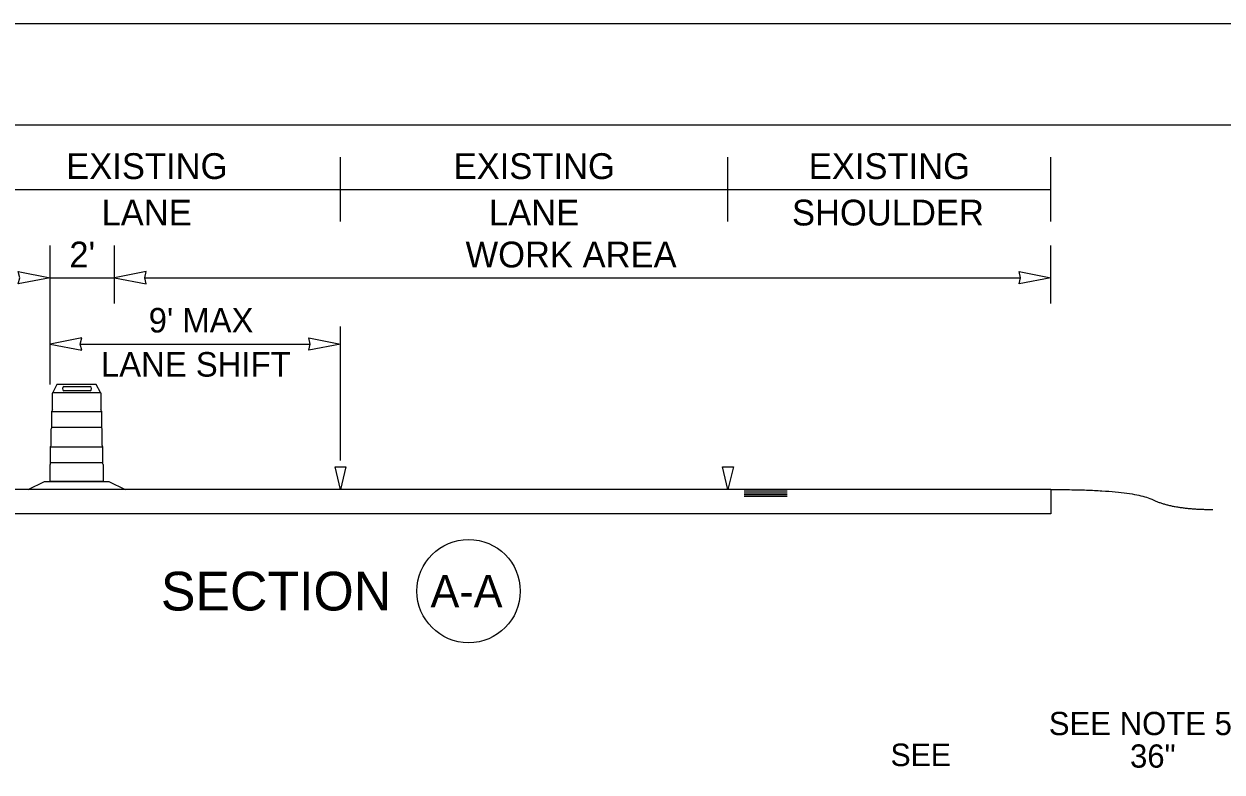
# Model space of a CAD drawing. Extents: x 99999 to 100116, y 99995 to 100013.
# Drawn here: x 100006.677 to 100010.388, y 100008.369 to 100010.687 of the extents above; entities that cross this region are included whole.
import ezdxf

# ---------------------------------------------------------------- set-up
doc = ezdxf.new("R2010")
doc.units = 0
for name, color, linetype in [('SH_GI_PlotLimits', 7, 'Continuous'), ('SH_GI_SheetBorder', 7, 'Continuous'), ('SH_TI_WZSectionCut', 7, 'Continuous'), ('TR_SN_ConstructionSigns', 7, 'Continuous'), ('TR_WZ_TrafficSafetyDrumElev', 7, 'Continuous')]:
    doc.layers.add(name, color=color, linetype=linetype)

msp = doc.modelspace()

# ---------------------------------------------------------------- linework, layer by layer
at = {"layer": 'SH_GI_PlotLimits'}
msp.add_lwpolyline([(99999.0625, 99999.6875), (100016.0625, 99999.6875), (100016.0625, 100010.6875), (99999.0625, 100010.6875)], close=True, dxfattribs=at)
at = {"layer": 'SH_GI_SheetBorder'}
msp.add_line((100000, 100010.375), (100015.75, 100010.375), dxfattribs=at)
at = {"layer": 'SH_TI_WZSectionCut'}
for p, q in [((100007.6578, 100010.075), (100007.6578, 100010.275)), ((100008.8578, 100010.075), (100008.8578, 100010.275)), ((100009.8578, 100010.075), (100009.8578, 100010.275)), ((100006.4578, 100010.175), (100007.6578, 100010.175)), ((100007.6578, 100010.175), (100008.8578, 100010.175)), ((100008.8578, 100010.175), (100009.8578, 100010.175)), ((100006.7578, 100009.57), (100006.7578, 100010.001)), ((100006.9578, 100009.821), (100006.9578, 100010.001)), ((100009.8578, 100009.821), (100009.8578, 100010.001)), ((100006.7578, 100009.901), (100006.9578, 100009.901)), ((100007.0515, 100009.901), (100009.764, 100009.901)), ((100007.6578, 100009.3347), (100007.6578, 100009.75)), ((100006.8515, 100009.6955), (100007.564, 100009.6955)), ((100009.8578, 100009.2449), (100005.4578, 100009.2449)), ((100009.0408, 100009.2393), (100008.9078, 100009.2393)), ((100009.0408, 100009.2337), (100008.9078, 100009.2337)), ((100009.0408, 100009.228), (100008.9078, 100009.228)), ((100009.8578, 100009.2449), (100009.8578, 100009.1699)), ((100009.0408, 100009.2228), (100008.9078, 100009.2228)), ((100009.8578, 100009.1699), (100005.4578, 100009.1699))]:
    msp.add_line(p, q, dxfattribs=at)
for points in [[(100006.7578, 100009.901), (100006.6595, 100009.8817), (100006.664, 100009.901), (100006.6595, 100009.9203)], [(100006.9578, 100009.901), (100007.056, 100009.8817), (100007.0515, 100009.901), (100007.056, 100009.9203)], [(100009.8578, 100009.901), (100009.7595, 100009.8817), (100009.764, 100009.901), (100009.7595, 100009.9203)], [(100006.7578, 100009.6955), (100006.856, 100009.6762), (100006.8515, 100009.6955), (100006.856, 100009.7148)], [(100007.6578, 100009.6955), (100007.5595, 100009.6762), (100007.564, 100009.6955), (100007.5595, 100009.7148)], [(100007.6411, 100009.3147), (100007.6744, 100009.3147), (100007.6578, 100009.2449)], [(100008.8411, 100009.3147), (100008.8744, 100009.3147), (100008.8578, 100009.2449)]]:
    msp.add_lwpolyline(points, close=True, dxfattribs=at)
msp.add_circle((100008.0543, 100008.93), 0.16, dxfattribs=at)
msp.add_open_spline([(100009.8578, 100009.2449), (100010.1089, 100009.2451), (100010.2344, 100009.183), (100010.3599, 100009.1831)], degree=2, dxfattribs=at)
at = {"layer": 'TR_WZ_TrafficSafetyDrumElev'}
for p, q in [((100006.8006, 100009.564), (100006.8824, 100009.564)), ((100006.7661, 100009.545), (100006.9141, 100009.545)), ((100006.7661, 100009.545), (100006.9141, 100009.545)), ((100006.8824, 100009.551), (100006.8006, 100009.551)), ((100006.7633, 100009.4871), (100006.917, 100009.4871)), ((100006.7633, 100009.4372), (100006.7633, 100009.4871)), ((100006.917, 100009.4871), (100006.917, 100009.4372)), ((100006.917, 100009.4372), (100006.7633, 100009.4372)), ((100006.7596, 100009.377), (100006.9207, 100009.377)), ((100006.7596, 100009.3271), (100006.7596, 100009.377)), ((100006.9207, 100009.377), (100006.9207, 100009.3271)), ((100006.9207, 100009.3271), (100006.7596, 100009.3271))]:
    msp.add_line(p, q, dxfattribs=at)
for points in [[(100006.9141, 100009.545), (100006.901, 100009.57), (100006.7793, 100009.57), (100006.7661, 100009.545)], [(100006.6901, 100009.245), (100006.7404, 100009.27), (100006.9399, 100009.27), (100006.9901, 100009.245)]]:
    msp.add_lwpolyline(points, close=True, dxfattribs=at)
for points in [[(100006.7651, 100009.4915), (100006.7651, 100009.543)], [(100006.7651, 100009.4915), (100006.7651, 100009.543)], [(100006.9151, 100009.543), (100006.9151, 100009.4915)], [(100006.9151, 100009.543), (100006.9151, 100009.4915)], [(100006.7633, 100009.4365), (100006.7633, 100009.4878)], [(100006.7633, 100009.4365), (100006.7633, 100009.4878)], [(100006.917, 100009.4878), (100006.917, 100009.4365)], [(100006.917, 100009.4878), (100006.917, 100009.4365)], [(100006.7614, 100009.3814), (100006.7614, 100009.4327)], [(100006.7614, 100009.3814), (100006.7614, 100009.4327)], [(100006.9188, 100009.4327), (100006.9188, 100009.3814)], [(100006.9188, 100009.4327), (100006.9188, 100009.3814)], [(100006.7596, 100009.3264), (100006.7596, 100009.3777)], [(100006.7596, 100009.3264), (100006.7596, 100009.3777)], [(100006.9207, 100009.3777), (100006.9207, 100009.3264)], [(100006.9207, 100009.3777), (100006.9207, 100009.3264)], [(100006.9225, 100009.3226), (100006.9225, 100009.27), (100006.7578, 100009.27), (100006.7578, 100009.3226)], [(100006.9225, 100009.3226), (100006.9225, 100009.27), (100006.7578, 100009.27), (100006.7578, 100009.3226)]]:
    msp.add_lwpolyline(points, dxfattribs=at)
for centre, major_axis, ratio, start_param, end_param in [((100006.8006, 100009.5575), (0, 0.0065), 0.570305, 0, 3.141593), ((100006.8824, 100009.5575), (0, 0.0065), 0.570305, 3.141593, 6.283185), ((100006.7664, 100009.5426), (0, 0.00249), 0.493438, 0.177149, 1.393647), ((100006.7664, 100009.5426), (0, 0.00249), 0.493438, 0.177149, 1.393647), ((100006.9139, 100009.5426), (0, 0.00249), 0.493438, 4.889538, 6.106036), ((100006.9139, 100009.5426), (0, 0.00249), 0.493438, 4.889538, 6.106036), ((100006.7667, 100009.4846), (0, 0.00758), 0.493438, 0.4288, 1.141997), ((100006.7667, 100009.4846), (0, 0.00758), 0.493438, 0.4288, 1.141997), ((100006.9136, 100009.4846), (0, 0.00758), 0.493438, 5.141189, 5.854386), ((100006.9136, 100009.4846), (0, 0.00758), 0.493438, 5.141189, 5.854386), ((100006.7648, 100009.4296), (0, 0.00758), 0.493438, 0.4288, 1.141997), ((100006.7648, 100009.4296), (0, 0.00758), 0.493438, 0.4288, 1.141997), ((100006.9154, 100009.4296), (0, 0.00758), 0.493438, 5.141189, 5.854386), ((100006.9154, 100009.4296), (0, 0.00758), 0.493438, 5.141189, 5.854386), ((100006.763, 100009.3745), (0, 0.00758), 0.493438, 0.4288, 1.141997), ((100006.763, 100009.3745), (0, 0.00758), 0.493438, 0.4288, 1.141997), ((100006.9173, 100009.3745), (0, 0.00758), 0.493438, 5.141189, 5.854386), ((100006.9173, 100009.3745), (0, 0.00758), 0.493438, 5.141189, 5.854386), ((100006.7612, 100009.3195), (0, 0.00758), 0.493438, 0.4288, 1.141997), ((100006.7612, 100009.3195), (0, 0.00758), 0.493438, 0.4288, 1.141997), ((100006.9191, 100009.3195), (0, 0.00758), 0.493438, 5.141189, 5.854386), ((100006.9191, 100009.3195), (0, 0.00758), 0.493438, 5.141189, 5.854386)]:
    msp.add_ellipse(centre, major_axis=major_axis, ratio=ratio, start_param=start_param, end_param=end_param, dxfattribs=at)

# ---------------------------------------------------------------- texts
at = {"layer": 'SH_TI_WZSectionCut'}
for s, height, p in [('EXISTING', 0.08, (100006.808, 100010.207)), ('EXISTING', 0.08, (100008.008, 100010.207)), ('EXISTING', 0.08, (100009.108, 100010.207)), ('LANE', 0.08, (100006.9174, 100010.063)), ('LANE', 0.08, (100008.1174, 100010.063)), ('SHOULDER', 0.08, (100009.056, 100010.063)), ('SECTION', 0.12, (100007.1012, 100008.87)), ('A-A', 0.1, (100007.9364, 100008.88))]:
    msp.add_text(s, height=height, rotation=360, dxfattribs=at).set_placement(p)
for s, height, p in [("2'", 0.08, (100006.8177, 100009.933)), ('WORK AREA', 0.08, (100008.0449, 100009.933)), ("9' MAX", 0.076, (100007.0635, 100009.7315)), ('LANE SHIFT', 0.076, (100006.9157, 100009.5947))]:
    msp.add_text(s, height=height, dxfattribs=at).set_placement(p)
at = {"layer": 'TR_SN_ConstructionSigns'}
for s, height, p in [('SEE NOTE 5', 0.072, (100009.8515, 100008.4838)), ('SEE', 0.07, (100009.3611, 100008.3877)), ('36"', 0.072, (100010.103, 100008.383))]:
    msp.add_text(s, height=height, rotation=360, dxfattribs=at).set_placement(p)

doc.saveas('drawing.dxf')
